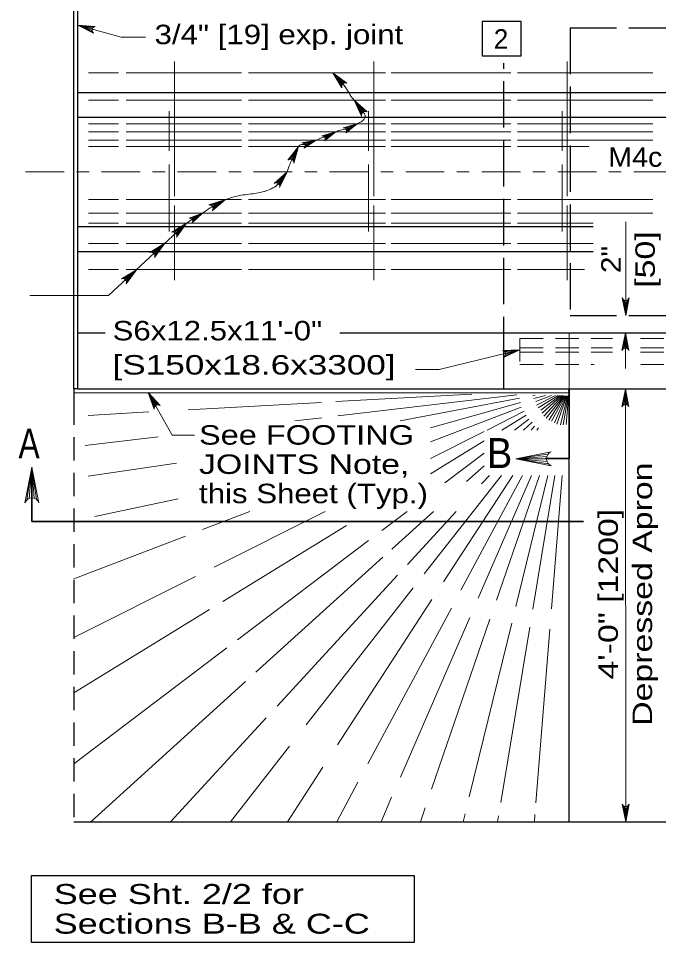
# Model space of a CAD drawing. Extents: x 1083.1 to 1123, y 697.4 to 741.4.
# Drawn here: x 1085.9 to 1091.03, y 729.39 to 736.8 of the extents above; entities that cross this region are included whole.
import ezdxf
from ezdxf.enums import TextEntityAlignment as Align

# ---------------------------------------------------------------- set-up
doc = ezdxf.new("R2010")
doc.units = 0
doc.header["$LTSCALE"] = 0.062
for name, pattern in [('DOT_DASHED', [7.7, 5, -1.2, 0.3, -1.2]), ('LONG_DASHED', [7.5, 6, -1.5]), ('MEDIUM_DASHED', [4.5, 3, -1.5])]:
    doc.linetypes.add(name, pattern=pattern)
doc.layers.add('1', color=7, linetype='Continuous', lineweight=13)

msp = doc.modelspace()

# ---------------------------------------------------------------- linework, layer by layer
at = {"layer": '1', "lineweight": 25}
for p, q in [((1086.34158, 733.92158), (1086.34158, 737.30308)), ((1086.37358, 733.92158), (1086.37358, 737.30308)), ((1086.37042, 736.21), (1096.93425, 736.21)), ((1086.37042, 736.01008), (1096.93425, 736.01008)), ((1086.37042, 735.13342), (1090.50625, 735.13342)), ((1086.37042, 734.93383), (1090.50625, 734.93383)), ((1086.37042, 734.28208), (1086.59175, 734.28208)), ((1088.474, 734.28208), (1096.92858, 734.28208)), ((1086.34158, 733.83392), (1086.34158, 733.92158)), ((1086.37358, 733.83392), (1086.37358, 733.92158)), ((1086.37358, 733.83392), (1086.34475, 733.83392)), ((1086.37042, 733.83392), (1090.3115, 733.83367)), ((1090.31492, 730.36267), (1090.31492, 733.83392)), ((1090.31492, 733.83392), (1090.507, 733.83392)), ((1090.507, 733.83392), (1091.12525, 733.83392)), ((1086.34158, 733.80242), (1090.3115, 733.80225)), ((1086.34158, 730.36267), (1102.18933, 730.36267))]:
    msp.add_line(p, q, dxfattribs=at)
at = {"layer": '1'}
for p, q in [((1086.48833, 736.7165), (1086.37358, 736.74758)), ((1086.48758, 736.70508), (1086.37358, 736.74758)), ((1086.49008, 736.696), (1086.37358, 736.74758)), ((1086.49192, 736.72467), (1086.37358, 736.74758)), ((1086.49825, 736.73175), (1086.37358, 736.74758)), ((1087.14908, 736.45767), (1087.14908, 735.3785)), ((1088.74833, 736.45767), (1088.74833, 735.3785)), ((1090.29958, 736.45767), (1090.29958, 735.3785)), ((1086.45783, 736.36533), (1086.69842, 736.36533)), ((1086.76183, 736.36533), (1087.68733, 736.36533)), ((1087.74183, 736.36533), (1088.84092, 736.36533)), ((1088.49967, 736.27892), (1088.41808, 736.36533)), ((1088.49308, 736.26967), (1088.41808, 736.36533)), ((1088.49042, 736.26067), (1088.41808, 736.36533)), ((1088.507, 736.28392), (1088.41808, 736.36533)), ((1088.51608, 736.28683), (1088.41808, 736.36533)), ((1088.88758, 736.36533), (1089.84642, 736.36533)), ((1089.90025, 736.36533), (1090.98575, 736.36533)), ((1086.45783, 736.14667), (1086.69842, 736.14667)), ((1086.76183, 736.14667), (1087.68733, 736.14667)), ((1087.74183, 736.14667), (1088.84092, 736.14667)), ((1088.66092, 736.05142), (1088.58967, 736.14667)), ((1088.65325, 736.04292), (1088.58967, 736.14667)), ((1088.64967, 736.03433), (1088.58967, 736.14667)), ((1088.66867, 736.05558), (1088.58967, 736.14667)), ((1088.67817, 736.05742), (1088.58967, 736.14667)), ((1088.88758, 736.14667), (1089.84642, 736.14667)), ((1089.90025, 736.14667), (1090.98575, 736.14667)), ((1087.10708, 736.05958), (1087.10708, 735.74183)), ((1088.70633, 736.05958), (1088.70633, 735.74183)), ((1090.25758, 736.05958), (1090.25758, 735.74183)), ((1086.45783, 735.95817), (1086.69842, 735.95817)), ((1086.76183, 735.95817), (1087.68733, 735.95817)), ((1087.74183, 735.95817), (1088.84092, 735.95817)), ((1088.51433, 735.92467), (1088.613, 735.95792)), ((1088.52083, 735.92067), (1088.613, 735.95792)), ((1088.52658, 735.91342), (1088.613, 735.95792)), ((1088.52883, 735.9065), (1088.613, 735.95792)), ((1088.529, 735.89867), (1088.613, 735.95792)), ((1088.88758, 735.95817), (1089.84642, 735.95817)), ((1089.90025, 735.95817), (1090.98575, 735.95817)), ((1086.45783, 735.89275), (1086.69842, 735.89275)), ((1086.76183, 735.89275), (1087.68733, 735.89275)), ((1087.74183, 735.89275), (1088.84092, 735.89275)), ((1088.34283, 735.861), (1088.44217, 735.89275)), ((1088.34933, 735.85683), (1088.44217, 735.89275)), ((1088.355, 735.8495), (1088.44217, 735.89275)), ((1088.35725, 735.8425), (1088.44217, 735.89275)), ((1088.35733, 735.83467), (1088.44217, 735.89275)), ((1088.88758, 735.89275), (1089.84642, 735.89275)), ((1089.90025, 735.89275), (1090.98575, 735.89275)), ((1086.45783, 735.82725), (1086.69842, 735.82725)), ((1086.76183, 735.82725), (1087.68733, 735.82725)), ((1087.74183, 735.82725), (1088.84092, 735.82725)), ((1088.183, 735.80267), (1088.28433, 735.82692)), ((1088.18908, 735.79817), (1088.28433, 735.82692)), ((1088.19425, 735.79033), (1088.28433, 735.82692)), ((1088.19542, 735.77542), (1088.28433, 735.82692)), ((1088.19592, 735.78325), (1088.28433, 735.82692)), ((1088.88758, 735.82725), (1089.84642, 735.82725)), ((1089.90025, 735.82725), (1090.98575, 735.82725)), ((1086.45783, 735.77675), (1086.69842, 735.77675)), ((1086.76183, 735.77675), (1087.68733, 735.77675)), ((1087.74183, 735.77675), (1088.84092, 735.77675)), ((1088.07008, 735.67308), (1088.14417, 735.77675)), ((1088.0795, 735.67367), (1088.14417, 735.77675)), ((1088.09042, 735.67058), (1088.14417, 735.77675)), ((1088.09767, 735.6655), (1088.14417, 735.77675)), ((1088.1035, 735.65783), (1088.14417, 735.77675)), ((1088.88758, 735.77675), (1089.84642, 735.77675)), ((1089.90025, 735.77675), (1090.472, 735.77675)), ((1087.10708, 735.63075), (1087.10708, 735.09325)), ((1088.70633, 735.63075), (1088.70633, 735.09325)), ((1090.25758, 735.63075), (1090.25758, 735.09325)), ((1087.96167, 735.48492), (1088.05317, 735.57342)), ((1087.97092, 735.48375), (1088.05317, 735.57342)), ((1087.98125, 735.47875), (1088.05317, 735.57342)), ((1087.98742, 735.47242), (1088.05317, 735.57342)), ((1087.99175, 735.46383), (1088.05317, 735.57342)), ((1086.45783, 735.35058), (1086.69842, 735.35058)), ((1086.76183, 735.35058), (1087.68733, 735.35058)), ((1087.14908, 735.30342), (1087.14908, 734.70342)), ((1087.43875, 735.30575), (1087.55792, 735.35058)), ((1087.44683, 735.30108), (1087.55792, 735.35058)), ((1087.45417, 735.29242), (1087.55792, 735.35058)), ((1087.45742, 735.28417), (1087.55792, 735.35058)), ((1087.45792, 735.2745), (1087.55792, 735.35058)), ((1087.74183, 735.35058), (1088.84092, 735.35058)), ((1088.74833, 735.30342), (1088.74833, 734.70342)), ((1088.88758, 735.35058), (1089.84642, 735.35058)), ((1089.90025, 735.35058), (1090.98575, 735.35058)), ((1090.29958, 735.30342), (1090.29958, 734.70342)), ((1086.45783, 735.24125), (1086.69842, 735.24125)), ((1086.76183, 735.24125), (1087.68733, 735.24125)), ((1087.27825, 735.201), (1087.37433, 735.24125)), ((1087.285, 735.19742), (1087.37433, 735.24125)), ((1087.29133, 735.1905), (1087.37433, 735.24125)), ((1087.29417, 735.18383), (1087.37433, 735.24125)), ((1087.29492, 735.17608), (1087.37433, 735.24125)), ((1087.74183, 735.24125), (1088.84092, 735.24125)), ((1088.88758, 735.24125), (1089.84642, 735.24125)), ((1089.90025, 735.24125), (1090.98575, 735.24125)), ((1086.45783, 735.162), (1086.69842, 735.162)), ((1086.76183, 735.162), (1087.68733, 735.162)), ((1087.14067, 735.09083), (1087.24633, 735.162)), ((1087.14967, 735.08808), (1087.24633, 735.162)), ((1087.15883, 735.08133), (1087.24633, 735.162)), ((1087.16383, 735.07408), (1087.24633, 735.162)), ((1087.16658, 735.06483), (1087.24633, 735.162)), ((1087.74183, 735.162), (1088.84092, 735.162)), ((1088.88758, 735.162), (1089.84642, 735.162)), ((1089.90025, 735.162), (1090.50625, 735.162)), ((1090.7685, 735.17225), (1090.7685, 734.42017)), ((1086.45783, 734.99958), (1086.69842, 734.99958)), ((1086.76183, 734.99958), (1087.68733, 734.99958)), ((1086.96467, 734.92867), (1087.07033, 734.99983)), ((1086.97367, 734.926), (1087.07033, 734.99983)), ((1086.98292, 734.91925), (1087.07033, 734.99983)), ((1086.98792, 734.91192), (1087.07033, 734.99983)), ((1086.99058, 734.90275), (1087.07033, 734.99983)), ((1087.74183, 734.99958), (1088.84092, 734.99958)), ((1088.88758, 734.99958), (1089.84642, 734.99958)), ((1089.90025, 734.99958), (1090.50625, 734.99958)), ((1086.45783, 734.78858), (1086.69842, 734.78858)), ((1086.73758, 734.71725), (1086.84325, 734.78833)), ((1086.74658, 734.7145), (1086.84325, 734.78833)), ((1086.75575, 734.70775), (1086.84325, 734.78833)), ((1086.76075, 734.70042), (1086.84325, 734.78833)), ((1086.76183, 734.78858), (1087.68733, 734.78858)), ((1086.7635, 734.69125), (1086.84325, 734.78833)), ((1087.74183, 734.78858), (1088.84092, 734.78858)), ((1088.88758, 734.78858), (1089.84642, 734.78858)), ((1089.90025, 734.78858), (1090.43833, 734.78858)), ((1090.75058, 734.54833), (1090.7685, 734.42017)), ((1090.78833, 734.54983), (1090.7685, 734.42017)), ((1090.78, 734.54492), (1090.7685, 734.42017)), ((1090.75942, 734.544), (1090.7685, 734.42017)), ((1090.7685, 734.54267), (1090.7685, 734.42017)), ((1090.31492, 734.28208), (1090.31492, 733.83392)), ((1090.74683, 734.15242), (1090.76667, 734.28208)), ((1090.75517, 734.15733), (1090.76667, 734.28208)), ((1090.76667, 734.15958), (1090.76667, 734.28208)), ((1090.77575, 734.15825), (1090.76667, 734.28208)), ((1089.7935, 734.13633), (1089.9205, 734.146)), ((1089.8, 734.1295), (1089.9205, 734.146)), ((1089.80325, 734.10092), (1089.9205, 734.146)), ((1089.80467, 734.11917), (1089.9205, 734.146)), ((1089.80533, 734.11025), (1089.9205, 734.146)), ((1086.34158, 733.83392), (1086.37042, 733.83392)), ((1090.31492, 733.83392), (1090.29183, 733.54658)), ((1090.31492, 733.83392), (1090.31, 733.80433)), ((1090.31492, 733.83392), (1090.31067, 733.8165)), ((1090.31492, 733.83392), (1090.31092, 733.82233)), ((1090.31492, 733.83392), (1090.31108, 733.82508)), ((1090.31492, 733.83392), (1090.31117, 733.82692)), ((1090.31492, 733.83392), (1090.31125, 733.82825)), ((1090.31492, 733.83392), (1090.31133, 733.83)), ((1090.31492, 733.83392), (1090.31133, 733.82925)), ((1090.31492, 733.83392), (1090.31142, 733.83217)), ((1090.31492, 733.83392), (1090.31142, 733.83175)), ((1090.31492, 733.83392), (1090.31142, 733.83125)), ((1090.31492, 733.83392), (1090.31142, 733.83067)), ((1090.31492, 733.83392), (1090.3115, 733.83367)), ((1090.31492, 733.83392), (1090.3115, 733.83325)), ((1090.31492, 733.83392), (1090.3115, 733.83292)), ((1090.31492, 733.83392), (1090.3115, 733.8335)), ((1090.31492, 733.83392), (1090.3115, 733.83258)), ((1090.74683, 733.70017), (1090.76667, 733.82983)), ((1090.75517, 733.70508), (1090.76667, 733.82983)), ((1090.76667, 733.82983), (1090.7685, 730.36267)), ((1090.76667, 733.70733), (1090.76667, 733.82983)), ((1090.77575, 733.706), (1090.76667, 733.82983)), ((1090.78458, 733.70167), (1090.76667, 733.82983)), ((1087.00008, 733.70058), (1086.93867, 733.80242)), ((1086.99167, 733.693), (1086.93867, 733.80242)), ((1086.98717, 733.68467), (1086.93867, 733.80242)), ((1087.00825, 733.704), (1086.93867, 733.80242)), ((1087.01775, 733.70483), (1086.93867, 733.80242)), ((1089.53525, 733.79075), (1088.4425, 733.73033)), ((1089.89483, 733.78467), (1088.45983, 733.61658)), ((1089.91675, 733.75842), (1088.95833, 733.57675)), ((1090.04225, 733.78225), (1090.02383, 733.77875)), ((1090.126, 733.78083), (1090.0325, 733.7545)), ((1090.17442, 733.78), (1090.0465, 733.73092)), ((1090.2065, 733.77942), (1090.05342, 733.70258)), ((1090.22558, 733.77908), (1090.067, 733.68183)), ((1090.24217, 733.77883), (1090.08825, 733.66242)), ((1090.25383, 733.77867), (1090.0985, 733.63817)), ((1090.26383, 733.7785), (1090.112, 733.61358)), ((1090.27142, 733.77833), (1090.13025, 733.598)), ((1090.27867, 733.77825), (1090.15142, 733.58267)), ((1090.285, 733.77808), (1090.17458, 733.57267)), ((1090.29067, 733.778), (1090.1965, 733.5615)), ((1090.29567, 733.77792), (1090.21733, 733.55017)), ((1090.30117, 733.77783), (1090.24425, 733.54558)), ((1090.30567, 733.77775), (1090.26717, 733.54483)), ((1088.3285, 733.724), (1087.25775, 733.66483)), ((1089.92475, 733.72425), (1089.20225, 733.52133)), ((1089.93033, 733.68633), (1089.20225, 733.40692)), ((1086.94392, 733.64742), (1086.45592, 733.62042)), ((1088.33, 733.60133), (1088.115, 733.57617)), ((1089.95517, 733.65317), (1089.65592, 733.50292)), ((1089.96983, 733.62217), (1089.7755, 733.50292)), ((1089.9925, 733.59), (1089.87742, 733.50292)), ((1090.018, 733.56533), (1089.949, 733.50292)), ((1090.0375, 733.53275), (1090.01008, 733.50292)), ((1090.06875, 733.5195), (1090.05583, 733.50292)), ((1087.0185, 733.44767), (1086.431, 733.37883)), ((1089.63258, 733.49117), (1089.20225, 733.275)), ((1089.63258, 733.41525), (1089.20225, 733.15125)), ((1089.63258, 733.31767), (1089.31792, 733.07967)), ((1090.14442, 733.30833), (1089.888, 733.2725)), ((1090.13567, 733.29058), (1089.888, 733.2725)), ((1087.16367, 733.23642), (1086.45533, 733.13425)), ((1089.63258, 733.21667), (1089.49258, 733.09008)), ((1090.13308, 733.2725), (1089.888, 733.2725)), ((1090.13758, 733.24942), (1089.888, 733.2725)), ((1090.14742, 733.23283), (1089.888, 733.2725)), ((1085.96533, 732.94358), (1086.005, 733.203)), ((1085.98192, 732.95342), (1086.005, 733.203)), ((1086.005, 732.95792), (1086.005, 733.203)), ((1086.02308, 732.95525), (1086.005, 733.203)), ((1086.04083, 732.94658), (1086.005, 733.203)), ((1089.771, 733.13917), (1089.15208, 732.34867)), ((1089.86267, 733.13917), (1089.30717, 732.28575)), ((1089.94167, 733.13917), (1089.44717, 732.21858)), ((1090.01283, 733.13917), (1089.58517, 732.15567)), ((1089.67492, 733.13917), (1089.612, 733.07092)), ((1090.076, 733.13917), (1089.73217, 732.13892)), ((1090.14458, 733.13917), (1089.88708, 732.08917)), ((1090.20008, 733.13917), (1090.02267, 732.06583)), ((1090.25908, 733.13917), (1090.17325, 732.06975)), ((1087.17733, 732.9525), (1086.50942, 732.80917)), ((1087.75183, 732.85025), (1087.374, 732.70525)), ((1088.35642, 732.85025), (1087.46817, 732.40408)), ((1089.01475, 732.85025), (1088.811, 732.69617)), ((1089.22733, 732.85025), (1088.89275, 732.54767)), ((1089.40867, 732.85025), (1089.01692, 732.425)), ((1088.52808, 732.73767), (1087.53608, 732.12908)), ((1087.236, 732.65233), (1086.34158, 732.30908)), ((1088.70525, 732.61617), (1087.6545, 731.82117)), ((1088.82142, 732.48317), (1087.80167, 731.56083)), ((1087.31825, 732.32875), (1086.34158, 731.83817)), ((1088.93783, 732.33908), (1087.9715, 731.29017)), ((1089.06483, 732.23725), (1088.20575, 731.14008)), ((1089.21408, 732.14283), (1088.45633, 730.97858)), ((1087.42925, 732.0635), (1086.34158, 731.39625)), ((1089.37017, 732.07533), (1088.6995, 730.82683)), ((1089.51783, 732.00083), (1088.96083, 730.71983)), ((1089.67942, 731.98575), (1089.21125, 730.62417)), ((1089.85417, 731.95467), (1089.51283, 730.56242)), ((1089.99867, 731.921), (1089.7665, 730.5165)), ((1090.16017, 731.90708), (1090.04825, 730.51392)), ((1087.5695, 731.75683), (1086.34158, 730.82792)), ((1087.71917, 731.48608), (1086.47708, 730.36267)), ((1087.88433, 731.19558), (1087.11708, 730.36267)), ((1088.07075, 730.96758), (1087.59717, 730.36267)), ((1088.3395, 730.79917), (1088.05542, 730.36267)), ((1088.62067, 730.68008), (1088.45017, 730.36267)), ((1088.89092, 730.55908), (1088.8055, 730.36267)), ((1089.15975, 730.47433), (1089.12133, 730.36267)), ((1090.75058, 730.49092), (1090.7685, 730.36267)), ((1090.75942, 730.48658), (1090.7685, 730.36267)), ((1090.78833, 730.49242), (1090.7685, 730.36267)), ((1090.78, 730.4875), (1090.7685, 730.36267)), ((1090.7685, 730.48525), (1090.7685, 730.36267)), ((1089.47942, 730.426), (1089.46383, 730.36267)), ((1089.749, 730.41075), (1089.74108, 730.36267)), ((1090.04067, 730.41908), (1090.03608, 730.36267))]:
    msp.add_line(p, q, dxfattribs=at)
at = {"layer": '1', "linetype": 'LONG_DASHED', "lineweight": 25}
for p, q in [((1090.32183, 736.72808), (1090.32183, 734.42017)), ((1089.79133, 734.03925), (1089.79133, 736.44533)), ((1089.79133, 733.83392), (1089.79133, 734.03925))]:
    msp.add_line(p, q, dxfattribs=at)
at = {"layer": '1', "linetype": 'DOT_DASHED'}
msp.add_line((1085.9535, 735.57342), (1096.93425, 735.57342), dxfattribs=at)
at = {"layer": '1', "linetype": 'MEDIUM_DASHED'}
for p, q in [((1089.9205, 734.23792), (1089.9205, 734.02792)), ((1089.9205, 734.23792), (1090.66217, 734.23792)), ((1090.888, 734.23792), (1091.27817, 734.23792)), ((1089.9205, 734.16067), (1090.66217, 734.16067)), ((1089.9205, 734.128), (1090.66217, 734.128)), ((1090.888, 734.16067), (1091.27817, 734.16067)), ((1090.888, 734.128), (1091.27817, 734.128)), ((1089.9205, 734.02792), (1090.51433, 734.02792)), ((1090.88917, 734.02792), (1096.92642, 734.02792))]:
    msp.add_line(p, q, dxfattribs=at)
at = {"layer": '1', "lineweight": 35}
for p, q in [((1090.31492, 733.83392), (1090.31492, 733.27425)), ((1090.19667, 733.27425), (1090.123, 733.27425)), ((1090.31492, 733.27425), (1090.19667, 733.27425)), ((1086.005, 733.203), (1086.005, 732.77033)), ((1090.42983, 732.77033), (1086.005, 732.77033))]:
    msp.add_line(p, q, dxfattribs=at)
at = {"layer": '1', "lineweight": 25}
for points in [[(1089.61683, 736.77942), (1089.61683, 736.50392), (1089.93117, 736.50392), (1089.93117, 736.77942)], [(1086.00275, 729.93183), (1089.07025, 729.93183), (1089.07025, 729.394), (1086.00275, 729.394)]]:
    msp.add_lwpolyline(points, close=True, dxfattribs=at)
at = {"layer": '1'}
for points in [[(1086.49908, 736.68508), (1086.37358, 736.74758), (1086.51342, 736.73817)], [(1086.37358, 736.74758), (1086.71967, 736.65192), (1086.91567, 736.65192)], [(1088.49242, 736.24658), (1088.41808, 736.36533), (1088.53233, 736.28425)], [(1088.65, 736.02008), (1088.58967, 736.14667), (1088.694, 736.053)], [(1088.50275, 735.92633), (1088.613, 735.95792), (1088.52342, 735.88642)], [(1088.33142, 735.86283), (1088.44217, 735.89275), (1088.35142, 735.82258)], [(1088.17158, 735.80533), (1088.28433, 735.82692), (1088.18867, 735.76383)], [(1088.05758, 735.6665), (1088.14417, 735.77675), (1088.10667, 735.64167)], [(1087.94808, 735.48067), (1088.05317, 735.57342), (1087.99192, 735.44733)], [(1087.42458, 735.30742), (1087.55792, 735.35058), (1087.4515, 735.25942)], [(1087.26667, 735.20183), (1087.37433, 735.24125), (1087.29008, 735.1635)], [(1087.24633, 735.162), (1086.61917, 734.58133), (1085.98842, 734.58133)], [(1087.12658, 735.089), (1087.24633, 735.162), (1087.16383, 735.04867)], [(1086.95067, 734.92692), (1087.07033, 734.99983), (1086.98792, 734.8865)], [(1086.7235, 734.71542), (1086.84325, 734.78833), (1086.76075, 734.675)], [(1090.79683, 734.56175), (1090.7685, 734.42017), (1090.74017, 734.56175)], [(1090.73833, 734.1405), (1090.76667, 734.28208), (1090.795, 734.1405)], [(1090.78458, 734.15392), (1090.76667, 734.28208), (1090.76667, 733.99675)], [(1089.9205, 734.146), (1089.27183, 733.98933), (1089.08275, 733.98933)], [(1089.78042, 734.14175), (1089.9205, 734.146), (1089.79283, 734.08825)], [(1090.73833, 733.68825), (1090.76667, 733.82983), (1090.795, 733.68825)], [(1086.98617, 733.67058), (1086.93867, 733.80242), (1087.03317, 733.69892)], [(1086.93867, 733.80242), (1087.13017, 733.46075), (1087.30975, 733.46075)], [(1090.17117, 733.21583), (1089.888, 733.2725), (1090.17117, 733.32908)], [(1085.94833, 732.91975), (1086.005, 733.203), (1086.06158, 732.91975)], [(1090.79683, 730.50433), (1090.7685, 730.36267), (1090.74017, 730.50433)]]:
    msp.add_lwpolyline(points, dxfattribs=at)
at = {"layer": '1', "linetype": 'LONG_DASHED', "lineweight": 25}
for points in [[(1090.32183, 736.72808), (1097.19325, 736.72808), (1098.25342, 736.72808)], [(1090.32183, 734.42017), (1097.16892, 734.42017), (1098.25342, 734.42017)]]:
    msp.add_lwpolyline(points, dxfattribs=at)
at = {"layer": '1', "linetype": 'MEDIUM_DASHED', "lineweight": 25}
msp.add_lwpolyline([(1086.34158, 733.83392), (1086.34158, 733.73183), (1086.34158, 730.36267)], dxfattribs=at)
at = {"layer": '1'}
for centre, radius, start, end in [((1090.76848, 734.57319), 0.03056, 202.08782, 337.91395), ((1090.76667, 734.12904), 0.03056, 22.08782, 157.91395), ((1090.76669, 733.67679), 0.03056, 22.08782, 157.91395), ((1090.19406, 733.27255), 0.06112, 112.08782, 247.91395), ((1086.00503, 732.8969), 0.06112, 22.08782, 157.91395), ((1090.76848, 730.51573), 0.03056, 202.08782, 337.91395)]:
    msp.add_arc(centre, radius, start, end, dxfattribs=at)
for centre, major_axis, start_param, end_param in [((1086.51699, 736.7087), (-0.02959, 0.00211), 4.9044669, 7.27508), ((1088.52003, 736.25729), (0.02966, 0), 1.1416719, 3.5122851), ((1088.67866, 736.02765), (0.02966, 0), 1.0276256, 3.3982387), ((1088.50493, 735.90225), (0.02427, 0), 5.5740102, 7.9446234), ((1088.17168, 735.78122), (0.02427, 0), 5.4836612, 7.8542744), ((1088.33325, 735.83865), (0.02427, 0), 5.5587602, 7.9293733), ((1088.07706, 735.64414), (0.02966, 0), 6.2002697, 8.5708828), ((1087.96326, 735.45515), (0.02966, 0), 6.0186602, 8.3892733), ((1087.42833, 735.27792), (0.02966, 0), 5.6086732, 7.9792863), ((1087.2706, 735.17789), (0.02427, 0), 5.6459012, 8.0165144), ((1087.13704, 735.0613), (0.02966, 0), 5.8425909, 8.213204), ((1086.96106, 734.89917), (0.02966, 0), 5.8425909, 8.213204), ((1086.73396, 734.68767), (0.02966, 0), 5.8425909, 8.213204), ((1089.77575, 734.11246), (0.02966, 0), 5.3254679, 7.6960811), ((1087.01537, 733.67515), (0.02324, 0.01843), 0.2575274, 2.6281405)]:
    msp.add_ellipse(centre, major_axis=major_axis, ratio=0.999895, start_param=start_param, end_param=end_param, dxfattribs=at)
for points in [[(1088.59025, 736.14583), (1088.55575, 736.19242), (1088.51808, 736.25492), (1088.47342, 736.30675), (1088.41808, 736.36533)], [(1088.61342, 735.95817), (1088.62292, 735.96408), (1088.64058, 735.97017), (1088.66433, 735.98925), (1088.67658, 736.009), (1088.67858, 736.02667), (1088.6725, 736.03825), (1088.64267, 736.07625), (1088.61275, 736.11575), (1088.58967, 736.14667)], [(1088.44217, 735.89275), (1088.46, 735.90158), (1088.50208, 735.91242), (1088.57683, 735.93417), (1088.61342, 735.95817)], [(1088.28492, 735.82725), (1088.31058, 735.8385), (1088.34808, 735.85225), (1088.38458, 735.86408), (1088.44217, 735.89275)], [(1088.14417, 735.77675), (1088.15392, 735.78725), (1088.18083, 735.79092), (1088.22617, 735.79583), (1088.28492, 735.82725)], [(1088.05317, 735.57342), (1088.07558, 735.63642), (1088.11592, 735.721), (1088.14417, 735.77675)], [(1087.55792, 735.35058), (1087.65142, 735.37883), (1087.77967, 735.39758), (1087.925, 735.437), (1087.97292, 735.46783), (1088.05317, 735.57342)], [(1087.37433, 735.24125), (1087.41833, 735.27233), (1087.55792, 735.35058)], [(1087.24633, 735.162), (1087.29983, 735.19575), (1087.37433, 735.24125)]]:
    msp.add_spline(points, degree=3, dxfattribs=at)

# ---------------------------------------------------------------- texts
for s, height, width, p in [('3/4" [19] exp. joint ', 0.156, 1.2, (1086.98883, 736.59642)), ('M4c', 0.156, 1.1, (1090.62883, 735.61325)), ('S6x12.5x11\'-0"', 0.156, 1.2, (1086.652, 734.22158)), ('[S150x18.6x3300]', 0.156, 1.35, (1086.652, 733.94758)), ('A', 0.24, 0.8, (1085.8965, 733.27467)), ('See FOOTING', 0.156, 1.25, (1087.34542, 733.38558)), ('B', 0.24, 0.95, (1089.655, 733.19817)), ('JOINTS Note,', 0.156, 1.3, (1087.34542, 733.15092)), ('this Sheet (Typ.)', 0.156, 1.2, (1087.34542, 732.91625)), ('See Sht. 2/2 for', 0.16, 1.35, (1086.17975, 729.703)), ('Sections B-B & C-C', 0.16, 1.35, (1086.17975, 729.465))]:
    msp.add_text(s, height=height, dxfattribs=dict(at, width=width)).set_placement(p)
msp.add_text('2', height=0.156, dxfattribs=at).set_placement((1089.71017, 736.56033))
for s, width, p in [('[50]', 1.3, (1091.00233, 734.86979)), ('2"', 1.15, (1090.72833, 734.86979)), ('Depressed Apron', 1.3, (1090.97992, 732.18687)), ('4\'-0" [1200]', 1.3, (1090.70592, 732.18687))]:
    msp.add_text(s, height=0.156, rotation=90, dxfattribs=dict(at, width=width)).set_placement(p, align=Align.CENTER)

doc.saveas('drawing.dxf')
